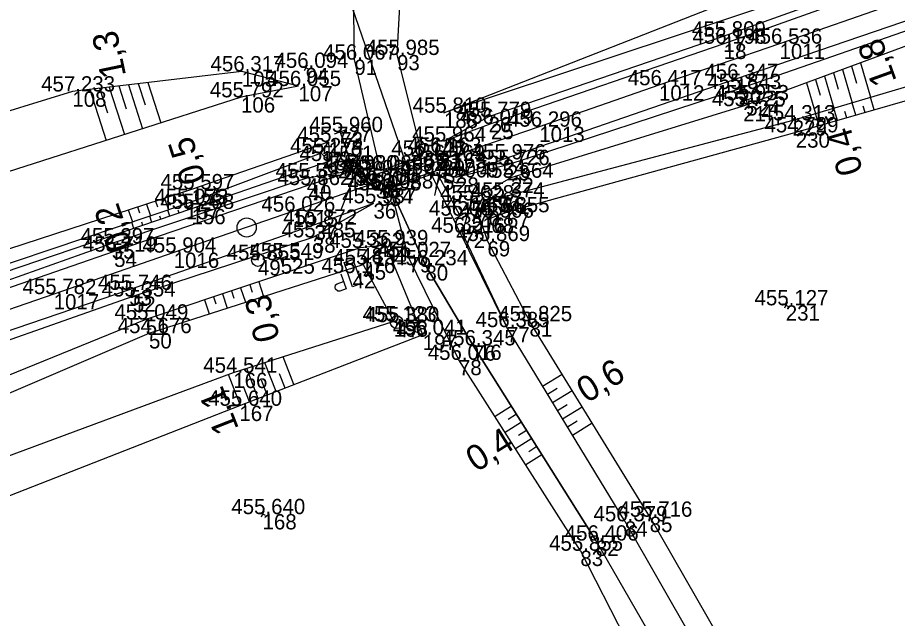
# Model space of a CAD drawing. Extents: x -751615 to -750797, y -1114905 to -1114561.
# Drawn here: x -750936.3 to -750867.3, y -1114640.8 to -1114593.7 of the extents above; entities that cross this region are included whole.
import ezdxf

# ---------------------------------------------------------------- set-up
doc = ezdxf.new("R2010")
doc.units = 0
for name, color, linetype in [('Vrstva 1', 7, 'Continuous'), ('Vrstva 33', 7, 'Continuous'), ('Vrstva 4', 7, 'Continuous'), ('Vrstva 48', 7, 'Continuous'), ('Vrstva 49', 7, 'Continuous'), ('Vrstva 51', 7, 'Continuous'), ('Vrstva 53', 7, 'Continuous'), ('Vrstva 60', 7, 'Continuous'), ('Vrstva 61', 7, 'Continuous'), ('Vrstva 7', 7, 'Continuous')]:
    doc.layers.add(name, color=color, linetype=linetype)

msp = doc.modelspace()

# ---------------------------------------------------------------- linework, layer by layer
at = {"layer": 'Vrstva 1'}
msp.add_lwpolyline([(-750820.337, -1114576.326), (-750829.58, -1114579.518), (-750838.838, -1114582.712), (-750848.38, -1114586.005), (-750858.075, -1114589.346), (-750867.336, -1114592.541), (-750876.526, -1114595.715), (-750885.989, -1114598.98), (-750895.385, -1114602.229), (-750902.991, -1114604.843), (-750908.211, -1114606.647), (-750914.742, -1114608.898), (-750924.077, -1114612.114), (-750933.495, -1114615.368), (-750942.896, -1114618.61), (-750952.239, -1114621.829), (-750961.799, -1114625.127), (-750971.586, -1114628.505), (-750981.562, -1114631.945), (-750991.246, -1114635.286), (-751001.048, -1114638.665), (-751010.672, -1114641.989), (-751020.123, -1114645.246), (-751029.869, -1114648.612)], dxfattribs=at)
at = {"layer": 'Vrstva 33'}
msp.add_lwpolyline([(-750909.349, -1114614.548), (-750910.053, -1114614.791), (-750910.709, -1114612.886), (-750910.005, -1114612.643)], close=True, dxfattribs=at)
msp.add_lwpolyline([(-750910.953, -1114613.779), (-750910.545, -1114614.965), (-750911.038, -1114615.135), (-750911.204, -1114615.137), (-750911.375, -1114614.981), (-750911.411, -1114614.876), (-750911.374, -1114614.644), (-750911.24, -1114614.55), (-750910.746, -1114614.38)], dxfattribs=at)
at = {"layer": 'Vrstva 4'}
for p, q in [((-750905.618, -1114605.751), (-750919.943, -1114564.3)), ((-750910.527, -1114602.486), (-750911.473, -1114602.812)), ((-750911, -1114602.649), (-750909.854, -1114605.974)), ((-750903.58, -1114607.625), (-750902.611, -1114603.118)), ((-750909.289, -1114604.545), (-750910.985, -1114608.831)), ((-750907.203, -1114607.528), (-750911.18, -1114605.197)), ((-750906.127, -1114605.024), (-750901.822, -1114606.671)), ((-750901.581, -1114609.214), (-750903.257, -1114606.122)), ((-750902.021, -1114609.452), (-750901.141, -1114608.976))]:
    msp.add_line(p, q, dxfattribs=at)
for points in [[(-750824.673, -1114575.386), (-750842.852, -1114581.727), (-750861.561, -1114588.189), (-750880.945, -1114595.155), (-750899.361, -1114601.468), (-750902.908, -1114603.401)], [(-750824.563, -1114575.932), (-750842.715, -1114582.202), (-750861.411, -1114588.769), (-750880.904, -1114595.722), (-750899.175, -1114602.016), (-750902.908, -1114603.401)], [(-750823.32, -1114578.973), (-750841.487, -1114585.259), (-750860.348, -1114591.764), (-750879.972, -1114598.494), (-750898.231, -1114604.794), (-750901.922, -1114606.212)], [(-750823.034, -1114579.626), (-750841.271, -1114586.102), (-750860.173, -1114592.481), (-750879.743, -1114599.276), (-750897.921, -1114605.245), (-750901.922, -1114606.212)], [(-750908.397, -1114606.03), (-750903.276, -1114604.273), (-750902.857, -1114605.474), (-750907.99, -1114607.236), (-750908.397, -1114606.03)], [(-750909.854, -1114605.662), (-750913.632, -1114606.277), (-750928.936, -1114611.392), (-750945.448, -1114617.255), (-750962.947, -1114623.179), (-750985.088, -1114630.83), (-751003.049, -1114637.15), (-751019.956, -1114643.079), (-751037.537, -1114649.178), (-751047.428, -1114652.085)], [(-750909.854, -1114605.662), (-750913.482, -1114606.81), (-750928.752, -1114612.038), (-750945.395, -1114617.786), (-750962.769, -1114623.789), (-750984.849, -1114631.395), (-751002.837, -1114637.648), (-751019.817, -1114643.56), (-751037.448, -1114649.672)], [(-750908.397, -1114608.245), (-750913.156, -1114610.918), (-750927.279, -1114615.559), (-750944.077, -1114621.468), (-750961.07, -1114627.222), (-750983.47, -1114634.851), (-751001.346, -1114641.244), (-751018.647, -1114647.092), (-751035.567, -1114652.973), (-751044.403, -1114656.035)], [(-750908.397, -1114608.245), (-750913.028, -1114609.922), (-750927.564, -1114615.039), (-750944.227, -1114620.718), (-750961.521, -1114626.651), (-750983.784, -1114634.327), (-751001.734, -1114640.382), (-751018.892, -1114646.443), (-751036.639, -1114652.467)]]:
    msp.add_lwpolyline(points, dxfattribs=at)
at = {"layer": 'Vrstva 48'}
for p, q in [((-750870.182, -1114597.225), (-750869.382, -1114599.922)), ((-750872.298, -1114598.005), (-750871.918, -1114599.284)), ((-750871.593, -1114597.745), (-750870.82, -1114600.349)), ((-750870.887, -1114597.485), (-750870.494, -1114598.81)), ((-750873.708, -1114598.525), (-750873.343, -1114599.757)), ((-750873.003, -1114598.265), (-750872.258, -1114600.776)), ((-750930.65, -1114599.304), (-750929.373, -1114603.304)), ((-750929.892, -1114599.214), (-750929.275, -1114601.145)), ((-750929.133, -1114599.123), (-750927.944, -1114602.848)), ((-750928.375, -1114599.033), (-750927.802, -1114600.826)), ((-750927.616, -1114598.943), (-750926.515, -1114602.391)), ((-750926.858, -1114598.853), (-750926.329, -1114600.508)), ((-750926.099, -1114598.762), (-750925.086, -1114601.935)), ((-750874.413, -1114598.785), (-750873.696, -1114601.202)), ((-750869.094, -1114600.905), (-750869.377, -1114599.921)), ((-750871.977, -1114601.734), (-750872.253, -1114600.774)), ((-750870.536, -1114601.319), (-750870.815, -1114600.348)), ((-750869.815, -1114601.112), (-750869.956, -1114600.623)), ((-750873.419, -1114602.149), (-750873.692, -1114601.201)), ((-750872.698, -1114601.941), (-750872.835, -1114601.464)), ((-750871.257, -1114601.527), (-750871.395, -1114601.044)), ((-750924.075, -1114607.602), (-750923.922, -1114608.057)), ((-750923.392, -1114607.38), (-750923.059, -1114608.27)), ((-750926.215, -1114608.298), (-750925.901, -1114609.231)), ((-750925.502, -1114608.066), (-750925.346, -1114608.529)), ((-750924.789, -1114607.834), (-750924.479, -1114608.752)), ((-750922.93, -1114608.771), (-750923.11, -1114608.29)), ((-750927.641, -1114608.763), (-750927.323, -1114609.709)), ((-750926.928, -1114608.53), (-750926.77, -1114609)), ((-750924.367, -1114609.259), (-750924.532, -1114608.769)), ((-750923.657, -1114609.018), (-750923.739, -1114608.774)), ((-750927.208, -1114610.223), (-750927.375, -1114609.727)), ((-750926.497, -1114609.982), (-750926.581, -1114609.735)), ((-750925.787, -1114609.741), (-750925.953, -1114609.248)), ((-750925.077, -1114609.5), (-750925.16, -1114609.254)), ((-750917.398, -1114614.403), (-750917.016, -1114615.547)), ((-750919.532, -1114615.116), (-750919.346, -1114615.675)), ((-750918.821, -1114614.878), (-750918.445, -1114616.005)), ((-750918.11, -1114614.641), (-750917.92, -1114615.208)), ((-750921.666, -1114615.829), (-750921.301, -1114616.922)), ((-750920.955, -1114615.591), (-750920.771, -1114616.142)), ((-750920.244, -1114615.354), (-750919.873, -1114616.463)), ((-750916.038, -1114623.017), (-750916.914, -1114620.75)), ((-750914.639, -1114622.476), (-750915.483, -1114620.292)), ((-750917.437, -1114623.558), (-750918.346, -1114621.208)), ((-750918.836, -1114624.099), (-750919.77, -1114621.682)), ((-750916.737, -1114623.287), (-750917.184, -1114622.133)), ((-750915.338, -1114622.746), (-750915.768, -1114621.634)), ((-750895.119, -1114622.584), (-750893.597, -1114621.648)), ((-750918.136, -1114623.828), (-750918.599, -1114622.633)), ((-750894.729, -1114623.225), (-750893.967, -1114622.756)), ((-750894.34, -1114623.866), (-750892.811, -1114622.926)), ((-750897.576, -1114624.161), (-750898.857, -1114624.976)), ((-750893.951, -1114624.507), (-750893.185, -1114624.036)), ((-750893.562, -1114625.148), (-750892.026, -1114624.204)), ((-750897.177, -1114624.796), (-750897.816, -1114625.203)), ((-750896.777, -1114625.431), (-750898.052, -1114626.242)), ((-750893.172, -1114625.789), (-750892.403, -1114625.316)), ((-750892.783, -1114626.43), (-750891.24, -1114625.482)), ((-750896.378, -1114626.066), (-750897.014, -1114626.47)), ((-750895.978, -1114626.701), (-750897.247, -1114627.508)), ((-750895.579, -1114627.336), (-750896.212, -1114627.738)), ((-750895.179, -1114627.97), (-750896.442, -1114628.773))]:
    msp.add_line(p, q, dxfattribs=at)
at = {"layer": 'Vrstva 49'}
for p, q in [((-750913.489, -1114597.724), (-750913.939, -1114597.504)), ((-750913.604, -1114597.389), (-750913.824, -1114597.839)), ((-750912.493, -1114604.315), (-750911.92, -1114603.429)), ((-750911.92, -1114603.429), (-750911.848, -1114604.924)), ((-750912.493, -1114604.315), (-750911.848, -1114604.924)), ((-750907.433, -1114611.535), (-750909.195, -1114613.036)), ((-750904.524, -1114618.563), (-750907.433, -1114611.535)), ((-750899.453, -1114611.209), (-750896.148, -1114617.498)), ((-750875.809, -1114616.36), (-750876.259, -1114616.14)), ((-750875.924, -1114616.025), (-750876.144, -1114616.475)), ((-750906.794, -1114617.513), (-750904.524, -1114618.563)), ((-750888.672, -1114633.201), (-750897.925, -1114617.962)), ((-750886.717, -1114632.841), (-750896.148, -1114617.498)), ((-750916.877, -1114632.748), (-750917.327, -1114632.528)), ((-750916.992, -1114632.413), (-750917.212, -1114632.863)), ((-750888.672, -1114633.201), (-750881.58, -1114645.562)), ((-750886.717, -1114632.841), (-750879.898, -1114644.696)), ((-750890.937, -1114634.713), (-750885.684, -1114643.833)), ((-750892.157, -1114635.509), (-750887.082, -1114645.369))]:
    msp.add_line(p, q, dxfattribs=at)
for points in [[(-750902.869, -1114601.131), (-750876.43, -1114590.758), (-750847.082, -1114577.508), (-750846.11, -1114576.392), (-750828.341, -1114569.281)], [(-750829.333, -1114576.055), (-750875.877, -1114592.182), (-750902.869, -1114601.131)], [(-750823, -1114580.577), (-750841.163, -1114586.823), (-750860.183, -1114593.537), (-750879.382, -1114600.618), (-750897.603, -1114606.242), (-750900.708, -1114608.016), (-750901.423, -1114610.555), (-750897.925, -1114617.962)], [(-750826.229, -1114587.12), (-750875.492, -1114601.735), (-750898.314, -1114607.786)], [(-750825.879, -1114588.474), (-750875.252, -1114602.676), (-750897.922, -1114608.949)], [(-750914.284, -1114599.037), (-750918.732, -1114597.886), (-750932.03, -1114599.468), (-750940.019, -1114601.94), (-750946.634, -1114602.952), (-750964.627, -1114605.55), (-750992.361, -1114614.436), (-751007.031, -1114618.887), (-751017.906, -1114622.672), (-751017.405, -1114633.573)], [(-750914.284, -1114599.037), (-750918.793, -1114599.925), (-750945.255, -1114608.376), (-750965.923, -1114618.296), (-750985.53, -1114625.726), (-750999.654, -1114628.771), (-751012.193, -1114628.621), (-751015.037, -1114629.632), (-751017.405, -1114633.573)], [(-750971.64, -1114623.079), (-750922.658, -1114607.141), (-750911.92, -1114603.429)], [(-750912.493, -1114604.315), (-750923.138, -1114608.3), (-750971.049, -1114624.437)], [(-750911.848, -1114604.924), (-750922.676, -1114608.685), (-750970.963, -1114625.07)], [(-750892.157, -1114635.509), (-750901.685, -1114620.531), (-750905.65, -1114612.465), (-750907.049, -1114607.083)], [(-750890.937, -1114634.713), (-750900.575, -1114619.395), (-750904.321, -1114613.107), (-750907.049, -1114607.083)], [(-750898.314, -1114607.786), (-750900.251, -1114608.825), (-750899.453, -1114611.209)], [(-750899.453, -1114611.209), (-750899.152, -1114609.372), (-750897.922, -1114608.949)], [(-750907.433, -1114611.535), (-750909.429, -1114611.74), (-750926.275, -1114617.369), (-750943.057, -1114624.185), (-750961.128, -1114630.505), (-750978.395, -1114636.117), (-750986.658, -1114639.578), (-751016.335, -1114647.709)], [(-750986.658, -1114639.578), (-750977.954, -1114637.558), (-750960.694, -1114632.291), (-750942.145, -1114625.351), (-750926.015, -1114618.435), (-750909.195, -1114613.036), (-750906.794, -1114617.513)], [(-750906.794, -1114617.513), (-750919.397, -1114621.544), (-750967.828, -1114639.504)], [(-750904.524, -1114618.563), (-750918.921, -1114624.132), (-750966.612, -1114642.791)]]:
    msp.add_lwpolyline(points, dxfattribs=at)
at = {"layer": 'Vrstva 51'}
msp.add_line((-750888.672, -1114633.201), (-750897.925, -1114617.962), dxfattribs=at)
for points in [[(-750907.847, -1114605.676), (-750909.898, -1114596.967), (-750910.005, -1114587.848), (-750908.734, -1114583.94), (-750904.958, -1114578.749), (-750901.36, -1114576.145), (-750861.222, -1114573.82)], [(-750907.847, -1114605.676), (-750904.542, -1114604.506), (-750906.55, -1114596.602), (-750906.082, -1114588.417), (-750904.868, -1114585.385), (-750901.781, -1114581.531), (-750899.088, -1114579.21), (-750860.591, -1114576.435)], [(-750897.925, -1114617.962), (-750903.836, -1114605.98), (-750907.049, -1114607.083)], [(-750907.049, -1114607.083), (-750904.321, -1114613.107), (-750900.575, -1114619.395), (-750890.937, -1114634.713)]]:
    msp.add_lwpolyline(points, dxfattribs=at)
at = {"layer": 'Vrstva 53'}
msp.add_line((-750906.533, -1114617.555), (-750906.627, -1114617.587), dxfattribs=at)
msp.add_circle((-750906.58, -1114617.571), 0.499, dxfattribs=at)
at = {"layer": 'Vrstva 60'}
for p, q in [((-750880.945, -1114595.155), (-750880.945, -1114595.155)), ((-750880.904, -1114595.722), (-750880.904, -1114595.722)), ((-750876.526, -1114595.715), (-750876.526, -1114595.715)), ((-750906.55, -1114596.602), (-750906.55, -1114596.602)), ((-750909.898, -1114596.967), (-750909.898, -1114596.967)), ((-750918.732, -1114597.886), (-750918.732, -1114597.886)), ((-750913.714, -1114597.614), (-750913.714, -1114597.614)), ((-750879.972, -1114598.494), (-750879.972, -1114598.494)), ((-750914.284, -1114599.037), (-750914.284, -1114599.037)), ((-750885.989, -1114598.98), (-750885.989, -1114598.98)), ((-750879.743, -1114599.276), (-750879.743, -1114599.276)), ((-750932.03, -1114599.468), (-750932.03, -1114599.468)), ((-750918.793, -1114599.925), (-750918.793, -1114599.925)), ((-750879.382, -1114600.618), (-750879.382, -1114600.618)), ((-750879.136, -1114600.158), (-750879.136, -1114600.158)), ((-750902.869, -1114601.131), (-750902.869, -1114601.131)), ((-750899.361, -1114601.468), (-750899.361, -1114601.468)), ((-750899.175, -1114602.016), (-750899.175, -1114602.016)), ((-750875.492, -1114601.735), (-750875.492, -1114601.735)), ((-750911, -1114602.649), (-750911, -1114602.649)), ((-750895.385, -1114602.229), (-750895.385, -1114602.229)), ((-750875.252, -1114602.676), (-750875.252, -1114602.676)), ((-750911.92, -1114603.429), (-750911.92, -1114603.429)), ((-750902.908, -1114603.401), (-750902.908, -1114603.401)), ((-750912.493, -1114604.315), (-750912.493, -1114604.315)), ((-750911.848, -1114604.924), (-750911.848, -1114604.924)), ((-750904.542, -1114604.506), (-750904.542, -1114604.506)), ((-750903.276, -1114604.273), (-750903.276, -1114604.273)), ((-750902.991, -1114604.843), (-750902.991, -1114604.843)), ((-750898.231, -1114604.794), (-750898.231, -1114604.794)), ((-750902.857, -1114605.474), (-750902.857, -1114605.474)), ((-750897.921, -1114605.245), (-750897.921, -1114605.245)), ((-750913.632, -1114606.277), (-750913.632, -1114606.277)), ((-750909.854, -1114605.662), (-750909.854, -1114605.662)), ((-750908.397, -1114606.03), (-750908.397, -1114606.03)), ((-750907.847, -1114605.676), (-750907.847, -1114605.676)), ((-750903.836, -1114605.98), (-750903.836, -1114605.98)), ((-750901.922, -1114606.212), (-750901.922, -1114606.212)), ((-750897.603, -1114606.242), (-750897.603, -1114606.242)), ((-750913.482, -1114606.81), (-750913.482, -1114606.81)), ((-750908.211, -1114606.647), (-750908.211, -1114606.647)), ((-750922.658, -1114607.141), (-750922.658, -1114607.141)), ((-750907.99, -1114607.236), (-750907.99, -1114607.236)), ((-750907.049, -1114607.083), (-750907.049, -1114607.083)), ((-750923.138, -1114608.3), (-750923.138, -1114608.3)), ((-750908.397, -1114608.245), (-750908.397, -1114608.245)), ((-750900.708, -1114608.016), (-750900.708, -1114608.016)), ((-750898.314, -1114607.786), (-750898.314, -1114607.786)), ((-750922.676, -1114608.685), (-750922.676, -1114608.685)), ((-750914.742, -1114608.898), (-750914.742, -1114608.898)), ((-750900.251, -1114608.825), (-750900.251, -1114608.825)), ((-750897.922, -1114608.949), (-750897.922, -1114608.949)), ((-750901.581, -1114609.214), (-750901.581, -1114609.214)), ((-750899.152, -1114609.372), (-750899.152, -1114609.372)), ((-750913.028, -1114609.922), (-750913.028, -1114609.922)), ((-750913.156, -1114610.918), (-750913.156, -1114610.918)), ((-750901.423, -1114610.555), (-750901.423, -1114610.555)), ((-750928.936, -1114611.392), (-750928.936, -1114611.392)), ((-750909.429, -1114611.74), (-750909.429, -1114611.74)), ((-750907.433, -1114611.535), (-750907.433, -1114611.535)), ((-750899.453, -1114611.209), (-750899.453, -1114611.209)), ((-750928.752, -1114612.038), (-750928.752, -1114612.038)), ((-750924.077, -1114612.114), (-750924.077, -1114612.114)), ((-750905.65, -1114612.465), (-750905.65, -1114612.465)), ((-750917.464, -1114612.701), (-750917.464, -1114612.701)), ((-750915.674, -1114612.569), (-750915.674, -1114612.569)), ((-750909.195, -1114613.036), (-750909.195, -1114613.036)), ((-750904.321, -1114613.107), (-750904.321, -1114613.107)), ((-750910.029, -1114613.717), (-750910.029, -1114613.717)), ((-750927.564, -1114615.039), (-750927.564, -1114615.039)), ((-750933.495, -1114615.368), (-750933.495, -1114615.368)), ((-750927.279, -1114615.559), (-750927.279, -1114615.559)), ((-750876.034, -1114616.25), (-750876.034, -1114616.25)), ((-750926.275, -1114617.369), (-750926.275, -1114617.369)), ((-750906.794, -1114617.513), (-750906.794, -1114617.513)), ((-750906.58, -1114617.571), (-750906.58, -1114617.571)), ((-750897.925, -1114617.962), (-750897.925, -1114617.962)), ((-750896.148, -1114617.498), (-750896.148, -1114617.498)), ((-750926.015, -1114618.435), (-750926.015, -1114618.435)), ((-750904.524, -1114618.563), (-750904.524, -1114618.563)), ((-750900.575, -1114619.395), (-750900.575, -1114619.395)), ((-750901.685, -1114620.531), (-750901.685, -1114620.531)), ((-750919.397, -1114621.544), (-750919.397, -1114621.544)), ((-750918.921, -1114624.132), (-750918.921, -1114624.132)), ((-750917.102, -1114632.638), (-750917.102, -1114632.638)), ((-750888.672, -1114633.201), (-750888.672, -1114633.201)), ((-750886.717, -1114632.841), (-750886.717, -1114632.841)), ((-750890.937, -1114634.713), (-750890.937, -1114634.713)), ((-750892.157, -1114635.509), (-750892.157, -1114635.509))]:
    msp.add_line(p, q, dxfattribs=at)
at = {"layer": 'Vrstva 7'}
for p, q in [((-750878.663, -1114599.995), (-750879.609, -1114600.321)), ((-750878.973, -1114600.631), (-750879.299, -1114599.685)), ((-750915.201, -1114612.406), (-750916.147, -1114612.732)), ((-750915.511, -1114613.042), (-750915.837, -1114612.096)), ((-750917.417, -1114612.685), (-750917.511, -1114612.717))]:
    msp.add_line(p, q, dxfattribs=at)
for centre, radius in [((-750918.348, -1114610.14), 0.75), ((-750917.464, -1114612.701), 0.5)]:
    msp.add_circle(centre, radius, dxfattribs=at)

# ---------------------------------------------------------------- texts
at = {"layer": 'Vrstva 48'}
for s, rotation, p in [('1,3', 101.78432, (-750927.805, -1114598.208)), ('1,8', 109.7737, (-750867.307, -1114598.631)), ('0,4', 106.04773, (-750869.963, -1114605.732)), ('0,5', 108.0241, (-750921.525, -1114606.383)), ('0,2', 108.74337, (-750927.272, -1114611.62)), ('0,3', 103.47677, (-750915.735, -1114618.866)), ('0,6', 31.57812, (-750891.654, -1114623.97)), ('1,1', 111.36781, (-750918.933, -1114625.931)), ('0,4', 32.17787, (-750900.331, -1114629.39))]:
    msp.add_text(s, height=2, rotation=rotation, dxfattribs=at).set_placement(p)
at = {"layer": 'Vrstva 60'}
for s, p in [('17', (-750880.945, -1114596.355)), ('18', (-750880.904, -1114596.922)), ('1011', (-750876.526, -1114596.915)), ('93', (-750906.55, -1114597.802)), ('91', (-750909.898, -1114598.167)), ('105', (-750918.732, -1114599.086)), ('94', (-750913.714, -1114598.814)), ('19', (-750879.972, -1114599.694)), ('107', (-750914.284, -1114600.237)), ('1012', (-750885.989, -1114600.18)), ('20', (-750879.743, -1114600.476)), ('108', (-750932.03, -1114600.668)), ('106', (-750918.793, -1114601.125)), ('21', (-750879.382, -1114601.818)), ('524', (-750879.136, -1114601.358)), ('188', (-750902.869, -1114602.331)), ('26', (-750899.361, -1114602.668)), ('25', (-750899.175, -1114603.216)), ('229', (-750875.492, -1114602.935)), ('73', (-750911, -1114603.849)), ('1013', (-750895.385, -1114603.429)), ('230', (-750875.252, -1114603.876)), ('175', (-750911.92, -1114604.629)), ('27', (-750902.908, -1114604.601)), ('31', (-750903.276, -1114605.473)), ('176', (-750912.493, -1114605.515)), ('174', (-750911.848, -1114606.124)), ('92', (-750904.542, -1114605.706)), ('29', (-750902.991, -1114606.043)), ('24', (-750898.231, -1114605.994)), ('32', (-750902.857, -1114606.674)), ('23', (-750897.921, -1114606.445)), ('41', (-750913.632, -1114607.477)), ('39', (-750909.854, -1114606.862)), ('34', (-750908.397, -1114607.23)), ('90', (-750907.847, -1114606.876)), ('75', (-750903.836, -1114607.18)), ('28', (-750901.922, -1114607.412)), ('22', (-750897.603, -1114607.442)), ('40', (-750913.482, -1114608.01)), ('30', (-750908.211, -1114607.847)), ('155', (-750922.658, -1114608.341)), ('33', (-750907.99, -1114608.436)), ('74', (-750907.049, -1114608.283)), ('157', (-750923.138, -1114609.5)), ('36', (-750908.397, -1114609.445)), ('71', (-750900.708, -1114609.216)), ('66', (-750898.314, -1114608.986)), ('156', (-750922.676, -1114609.885)), ('1015', (-750914.742, -1114610.098)), ('70', (-750900.251, -1114610.025)), ('67', (-750897.922, -1114610.149)), ('35', (-750901.581, -1114610.414)), ('68', (-750899.152, -1114610.572)), ('37', (-750913.028, -1114611.122)), ('38', (-750913.156, -1114612.118)), ('72', (-750901.423, -1114611.755)), ('55', (-750928.936, -1114612.592)), ('48', (-750909.429, -1114612.94)), ('44', (-750907.433, -1114612.735)), ('69', (-750899.453, -1114612.409)), ('54', (-750928.752, -1114613.238)), ('1016', (-750924.077, -1114613.314)), ('79', (-750905.65, -1114613.665)), ('49', (-750917.464, -1114613.901)), ('525', (-750915.674, -1114613.769)), ('45', (-750909.195, -1114614.236)), ('80', (-750904.321, -1114614.307)), ('42', (-750910.029, -1114614.917)), ('53', (-750927.564, -1114616.239)), ('1017', (-750933.495, -1114616.568)), ('52', (-750927.279, -1114616.759)), ('231', (-750876.034, -1114617.45)), ('51', (-750926.275, -1114618.569)), ('198', (-750906.794, -1114618.713)), ('47', (-750906.58, -1114618.771)), ('77', (-750897.925, -1114619.162)), ('81', (-750896.148, -1114618.698)), ('50', (-750926.015, -1114619.635)), ('197', (-750904.524, -1114619.763)), ('76', (-750900.575, -1114620.595)), ('78', (-750901.685, -1114621.731)), ('166', (-750919.397, -1114622.744)), ('167', (-750918.921, -1114625.332)), ('168', (-750917.102, -1114633.838)), ('84', (-750888.672, -1114634.401)), ('85', (-750886.717, -1114634.041)), ('82', (-750890.937, -1114635.913)), ('83', (-750892.157, -1114636.709))]:
    msp.add_text(s, height=1.2, dxfattribs=at).set_placement(p)
at = {"layer": 'Vrstva 61'}
for s, p in [('455.809', (-750883.399, -1114595.155)), ('456.198', (-750883.358, -1114595.722)), ('456.536', (-750878.978, -1114595.715)), ('456.067', (-750912.35, -1114596.967)), ('455.985', (-750909.006, -1114596.602)), ('456.094', (-750916.165, -1114597.614)), ('456.317', (-750921.184, -1114597.886)), ('456.347', (-750882.424, -1114598.494)), ('456.055', (-750916.74, -1114599.037)), ('456.417', (-750888.441, -1114598.98)), ('457.233', (-750934.482, -1114599.468)), ('455.792', (-750921.241, -1114599.925)), ('455.843', (-750882.195, -1114599.276)), ('455.725', (-750881.838, -1114600.618)), ('455.953', (-750881.588, -1114600.158)), ('455.810', (-750905.32, -1114601.131)), ('455.779', (-750901.815, -1114601.468)), ('456.019', (-750901.629, -1114602.016)), ('454.313', (-750877.944, -1114601.735)), ('455.960', (-750913.451, -1114602.649)), ('456.296', (-750897.837, -1114602.229)), ('454.729', (-750877.706, -1114602.676)), ('455.964', (-750905.359, -1114603.401)), ('455.727', (-750914.372, -1114603.429)), ('455.274', (-750914.944, -1114604.315)), ('456.145', (-750906.998, -1114604.506)), ('456.163', (-750905.728, -1114604.273)), ('455.591', (-750914.205, -1114604.924)), ('456.169', (-750905.445, -1114604.843)), ('455.976', (-750900.683, -1114604.794)), ('455.726', (-750900.373, -1114605.245)), ('455.980', (-750912.305, -1114605.662)), ('456.099', (-750910.851, -1114606.03)), ('456.089', (-750910.301, -1114605.676)), ('456.147', (-750906.288, -1114605.98)), ('456.163', (-750905.309, -1114605.474)), ('455.592', (-750916.08, -1114606.277)), ('455.862', (-750915.93, -1114606.81)), ('456.100', (-750910.662, -1114606.647)), ('456.009', (-750904.376, -1114606.212)), ('455.664', (-750900.054, -1114606.242)), ('455.597', (-750925.11, -1114607.141)), ('456.098', (-750910.444, -1114607.236)), ('456.088', (-750909.503, -1114607.083)), ('455.628', (-750903.162, -1114608.016)), ('455.374', (-750900.765, -1114607.786)), ('455.073', (-750925.59, -1114608.3)), ('455.288', (-750925.13, -1114608.685)), ('456.026', (-750917.194, -1114608.898)), ('455.937', (-750910.849, -1114608.245)), ('455.496', (-750902.703, -1114608.825)), ('456.005', (-750904.037, -1114609.214)), ('455.906', (-750901.604, -1114609.372)), ('455.855', (-750900.378, -1114608.949)), ('455.872', (-750915.476, -1114609.922)), ('455.485', (-750915.612, -1114610.918)), ('456.216', (-750903.875, -1114610.555)), ('455.297', (-750931.388, -1114611.392)), ('455.939', (-750909.887, -1114611.535)), ('455.869', (-750901.907, -1114611.209)), ('455.719', (-750931.206, -1114612.038)), ('455.904', (-750926.528, -1114612.114)), ('455.362', (-750911.877, -1114611.74)), ('455.855', (-750919.92, -1114612.701)), ('455.549', (-750918.128, -1114612.569)), ('455.131', (-750911.552, -1114613.036)), ('456.027', (-750908.102, -1114612.465)), ('455.176', (-750912.481, -1114613.717)), ('456.234', (-750906.772, -1114613.107)), ('455.746', (-750930.016, -1114615.039)), ('455.782', (-750935.943, -1114615.368)), ('455.354', (-750929.73, -1114615.559)), ('455.127', (-750878.486, -1114616.25)), ('455.049', (-750928.729, -1114617.369)), ('455.123', (-750909.246, -1114617.513)), ('455.380', (-750909.031, -1114617.571)), ('455.825', (-750898.604, -1114617.498)), ('454.676', (-750928.467, -1114618.435)), ('456.041', (-750906.881, -1114618.563)), ('456.385', (-750900.381, -1114617.962)), ('456.345', (-750903.031, -1114619.395)), ('456.016', (-750904.137, -1114620.531)), ('454.541', (-750921.754, -1114621.544)), ('455.640', (-750921.372, -1114624.132)), ('455.640', (-750919.553, -1114632.638)), ('455.716', (-750889.169, -1114632.841)), ('456.379', (-750891.126, -1114633.201)), ('456.406', (-750893.389, -1114634.713)), ('455.855', (-750894.613, -1114635.509))]:
    msp.add_text(s, height=1.2, dxfattribs=at).set_placement(p)

doc.saveas('drawing.dxf')
